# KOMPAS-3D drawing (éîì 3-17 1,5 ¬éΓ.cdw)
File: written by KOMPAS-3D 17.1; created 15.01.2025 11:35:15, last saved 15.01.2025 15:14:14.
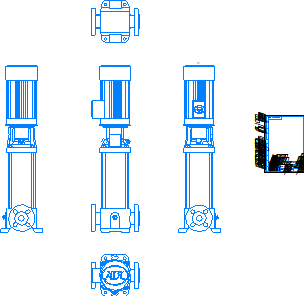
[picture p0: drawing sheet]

Sheet 1: A4, portrait

Title block, sheet 1: name: ВМН 3-17 1,5 кВт; designation: ВМН 3-17 1,5 кВт; material: Сталь 10  ГОСТ 1050-2013; mass: 68,16; sheets: 1; sheet format: A4; stored path: \\adlc.lan\data\АДЛ_ПКД\3D-модели\ADL production\Насосы ГРАНПАМП\Насосы ВМН\ВМН3\KOMPAS 3D\ВМН 3-17 1,5 кВт.cdw

Views: Проекционный вид 2, Проекционный вид 3, Проекционный вид 4, Проекционный вид 5
Referenced files in \\adlc.lan\data\АДЛ_ПКД\3D-модели\ADL production\Насосы ГРАНПАМП\Насосы ВМН\ВМН3\KOMPAS 3D\: ВМН 3-17 1,5кВт.m3d
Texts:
  Andrey
  АДЛ
Dimensions and other numbers on the sheet: 1:1; 1; 68,16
